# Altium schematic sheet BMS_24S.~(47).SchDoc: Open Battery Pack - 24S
size A3; Date: 26/03/2019; Author: Morgane Vallée - Samuel Lesueur; Revision: 1.0; SheetNumber: 3; SheetTotal: 5
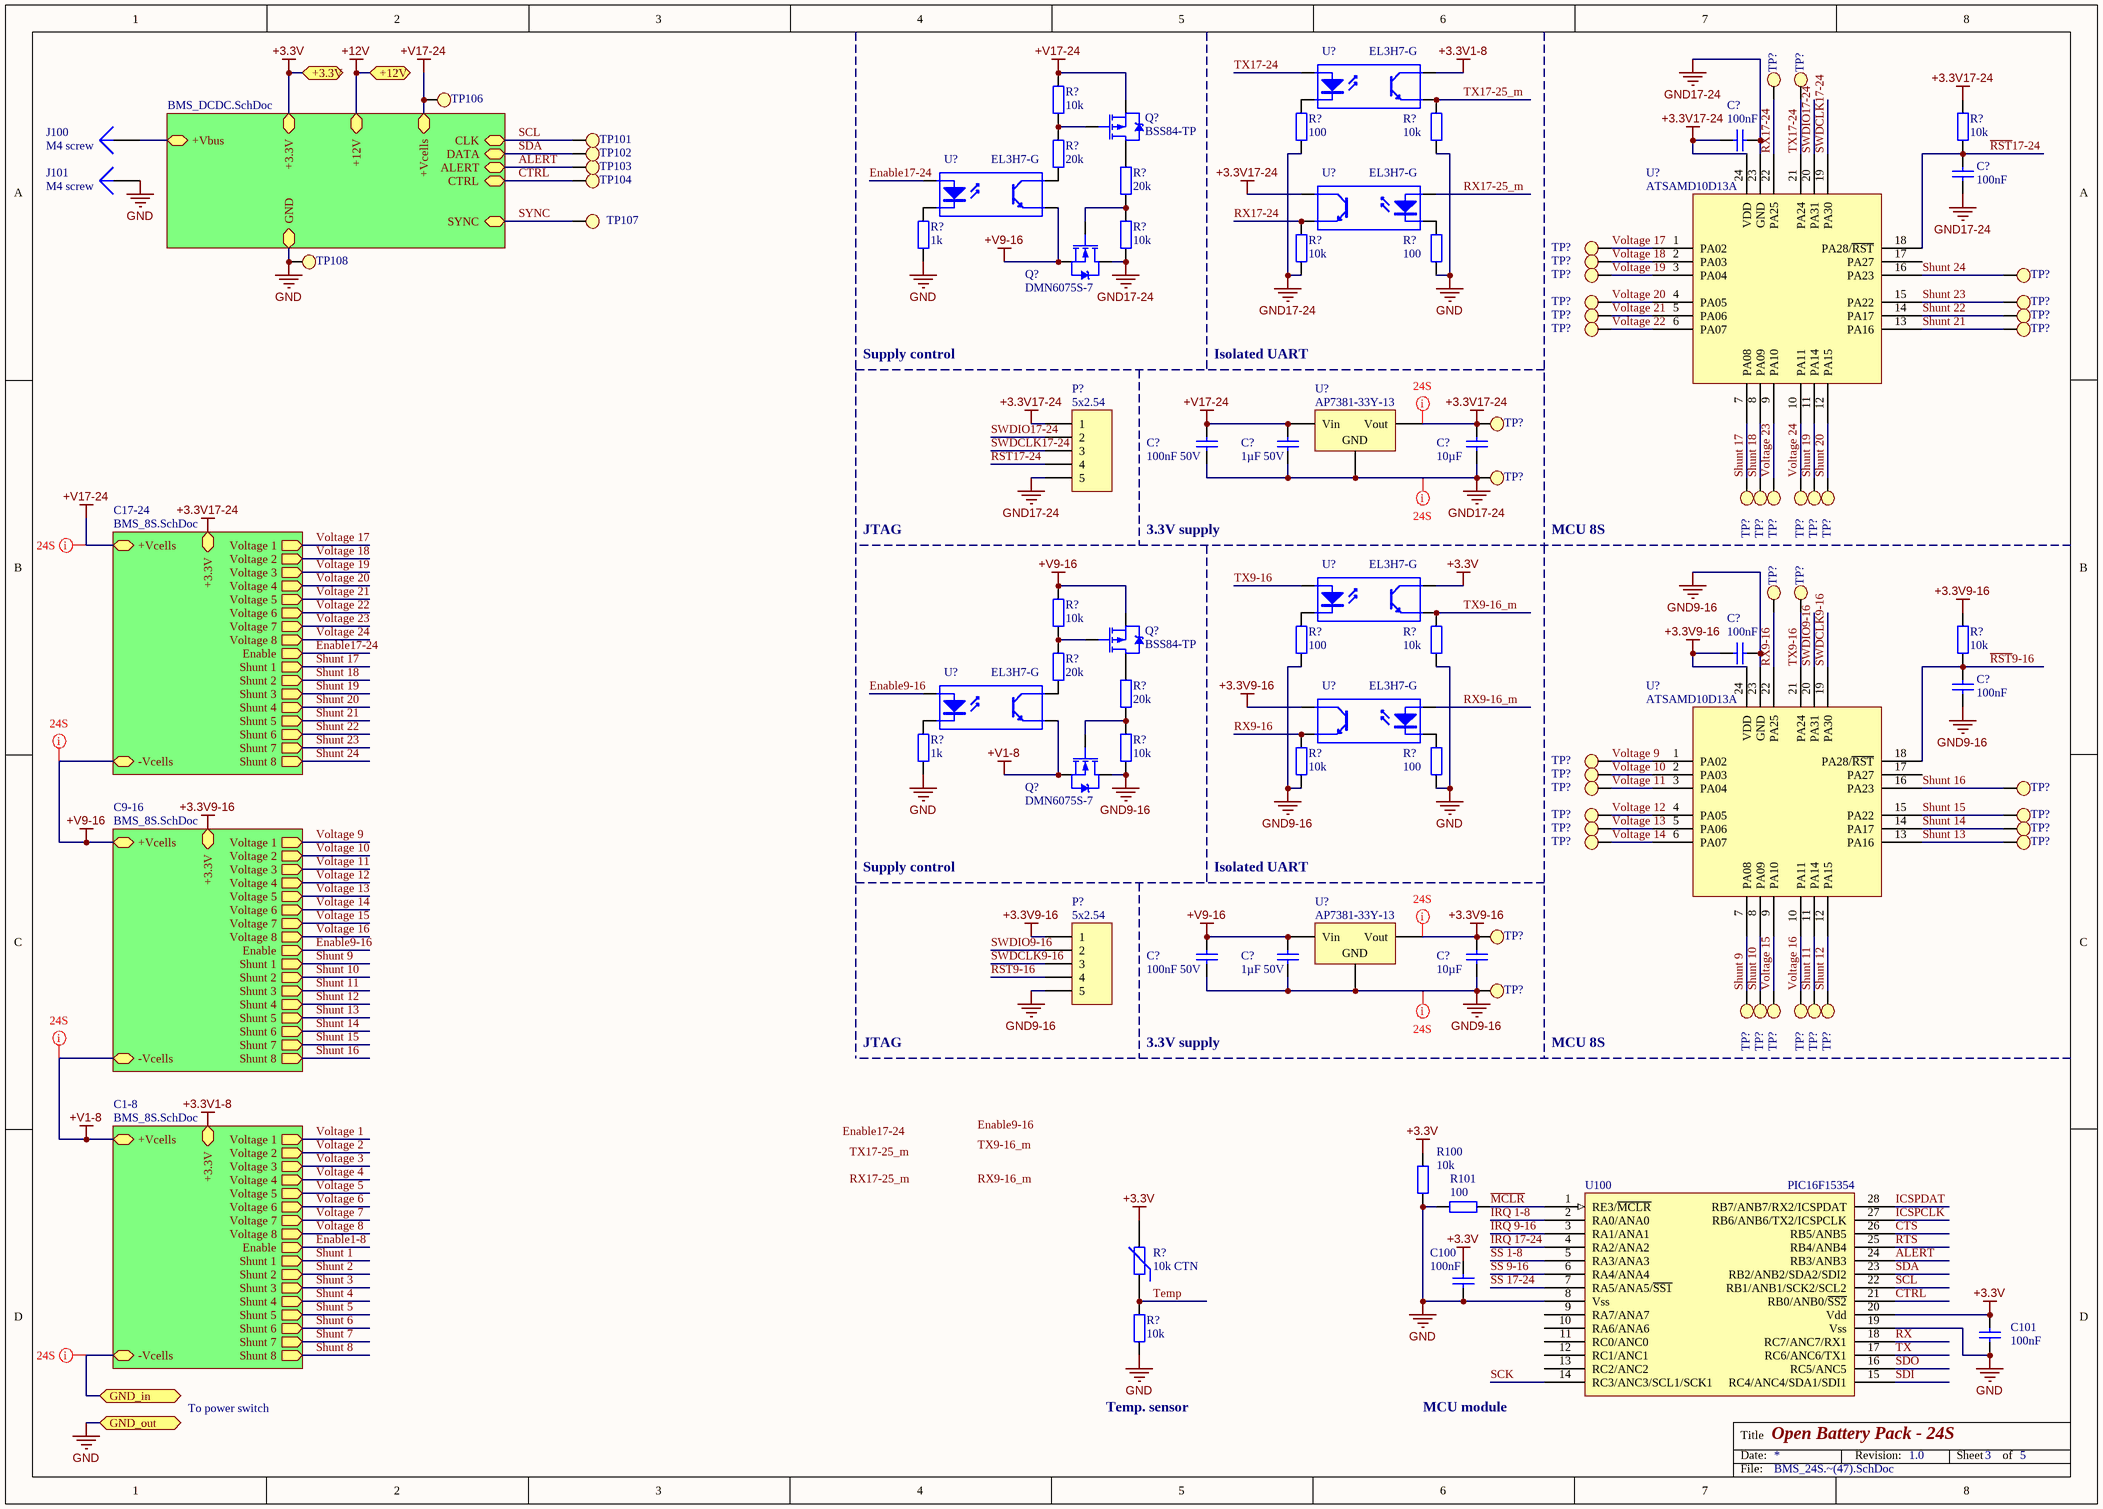
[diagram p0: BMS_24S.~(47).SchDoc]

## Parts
(Parts that share a designator on the sheet are numbered #1, #2 ... from top to bottom, then left to right.)
C100  100nF  [C0603]
C101  100nF  [C0603]
C?#1  100nF  [C0603]
C?#2  100nF  [C0603]
C?#3  100nF 50V  [C0603]
C?#4  1µF 50V  [C0805]
C?#5  10µF  [C0603]
C?#6  100nF  [C0603]
C?#7  100nF  [C0603]
C?#8  100nF 50V  [C0603]
C?#9  1µF 50V  [C0805]
C?#10  10µF  [C0603]
J100  M4 screw  [HOLE_4]
J101  M4 screw  [HOLE_4]
P?#1  5x2.54  [HDR1X5]
P?#2  5x2.54  [HDR1X5]
Q?#1  BSS84-TP  [DIODES SOT-23-3]
Q?#2  DMN6075S-7  [DIODES SOT-23-3]
Q?#3  BSS84-TP  [DIODES SOT-23-3]
Q?#4  DMN6075S-7  [DIODES SOT-23-3]
R100  10k  [R0603]
R101  100  [R0603]
R?#1  10k  [R0603]
R?#2  10k  [R0603]
R?#3  100  [R0603]
R?#4  10k  [R0603]
R?#5  20k  [R0603]
R?#6  20k  [R0603]
R?#7  100  [R0603]
R?#8  1k  [R0603]
R?#9  10k  [R0603]
R?#10  10k  [R0603]
R?#11  10k  [R0603]
R?#12  10k  [R0603]
R?#13  100  [R0603]
R?#14  10k  [R0603]
R?#15  20k  [R0603]
R?#16  20k  [R0603]
R?#17  100  [R0603]
R?#18  1k  [R0603]
R?#19  10k  [R0603]
R?#20  10k  [R0603]
R?#21  10k CTN  [NTC 0402/1005]
R?#22  10k  [R0603]
TP101  Test Point  [Test Point]  (value not drawn)
TP102  Test Point  [Test Point]  (value not drawn)
TP103  Test Point  [Test Point]  (value not drawn)
TP104  Test Point  [Test Point]  (value not drawn)
TP106  Test Point  [Test Point]  (value not drawn)
TP107  Test Point  [Test Point]  (value not drawn)
TP108  Test Point  [Test Point]  (value not drawn)
TP?#1  Test Point  [Test Point]  (value not drawn)
TP?#2  Test Point  [Test Point]  (value not drawn)
TP?#3  Test Point  [Test Point]  (value not drawn)
TP?#4  Test Point  [Test Point]  (value not drawn)
TP?#5  Test Point  [Test Point]  (value not drawn)
TP?#6  Test Point  [Test Point]  (value not drawn)
TP?#7  Test Point  [Test Point]  (value not drawn)
TP?#8  Test Point  [Test Point]  (value not drawn)
TP?#9  Test Point  [Test Point]  (value not drawn)
TP?#10  Test Point  [Test Point]  (value not drawn)
TP?#11  Test Point  [Test Point]  (value not drawn)
TP?#12  Test Point  [Test Point]  (value not drawn)
TP?#13  Test Point  [Test Point]  (value not drawn)
TP?#14  Test Point  [Test Point]  (value not drawn)
TP?#15  Test Point  [Test Point]  (value not drawn)
TP?#16  Test Point  [Test Point]  (value not drawn)
TP?#17  Test Point  [Test Point]  (value not drawn)
TP?#18  Test Point  [Test Point]  (value not drawn)
TP?#19  Test Point  [Test Point]  (value not drawn)
TP?#20  Test Point  [Test Point]  (value not drawn)
TP?#21  Test Point  [Test Point]  (value not drawn)
TP?#22  Test Point  [Test Point]  (value not drawn)
TP?#23  Test Point  [Test Point]  (value not drawn)
TP?#24  Test Point  [Test Point]  (value not drawn)
TP?#25  Test Point  [Test Point]  (value not drawn)
TP?#26  Test Point  [Test Point]  (value not drawn)
TP?#27  Test Point  [Test Point]  (value not drawn)
TP?#28  Test Point  [Test Point]  (value not drawn)
TP?#29  Test Point  [Test Point]  (value not drawn)
TP?#30  Test Point  [Test Point]  (value not drawn)
TP?#31  Test Point  [Test Point]  (value not drawn)
TP?#32  Test Point  [Test Point]  (value not drawn)
TP?#33  Test Point  [Test Point]  (value not drawn)
TP?#34  Test Point  [Test Point]  (value not drawn)
TP?#35  Test Point  [Test Point]  (value not drawn)
TP?#36  Test Point  [Test Point]  (value not drawn)
TP?#37  Test Point  [Test Point]  (value not drawn)
TP?#38  Test Point  [Test Point]  (value not drawn)
TP?#39  Test Point  [Test Point]  (value not drawn)
TP?#40  Test Point  [Test Point]  (value not drawn)
U100  PIC16F15354  [SSOP_28]
U?#1  EL3H7-G  [OPTO_EL3H7-G]
U?#2  EL3H7-G  [OPTO_EL3H7-G]
U?#3  EL3H7-G  [OPTO_EL3H7-G]
U?#4  ATSAMD10D13A  [SMSC QFN-24 4x4MM]
U?#5  AP7381-33Y-13  [ST SOIC-8N]
U?#6  EL3H7-G  [OPTO_EL3H7-G]
U?#7  EL3H7-G  [OPTO_EL3H7-G]
U?#8  EL3H7-G  [OPTO_EL3H7-G]
U?#9  ATSAMD10D13A  [SMSC QFN-24 4x4MM]
U?#10  AP7381-33Y-13  [ST SOIC-8N]

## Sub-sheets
C1-8 = BMS_8S.SchDoc: Voltage 6 (out), Shunt 2 (out), Shunt 7 (out), Shunt 6 (out), Voltage 3 (out), Voltage 5 (out), Shunt 8 (out), Voltage 8 (out), Voltage 7 (out), +3.3V, Voltage 2 (out), Shunt 4 (out), Shunt 3 (out), Shunt 5 (out), Voltage 4 (out), -Vcells, +Vcells, Shunt 1 (out), Voltage 1 (out), Enable (out)
C9-16 = BMS_8S.SchDoc: Voltage 6 (out), Shunt 2 (out), Shunt 7 (out), Shunt 6 (out), Voltage 3 (out), Voltage 5 (out), Shunt 8 (out), Voltage 8 (out), Voltage 7 (out), +3.3V, Voltage 2 (out), Shunt 4 (out), Shunt 3 (out), Shunt 5 (out), Voltage 4 (out), -Vcells, +Vcells, Shunt 1 (out), Voltage 1 (out), Enable (out)
C17-24 = BMS_8S.SchDoc: Voltage 6 (out), Shunt 2 (out), Shunt 7 (out), Shunt 6 (out), Voltage 3 (out), Voltage 5 (out), Shunt 8 (out), Voltage 8 (out), Voltage 7 (out), +3.3V, Voltage 2 (out), Shunt 4 (out), Shunt 3 (out), Shunt 5 (out), Voltage 4 (out), -Vcells, +Vcells, Shunt 1 (out), Voltage 1 (out), Enable (out)
? = BMS_DCDC.SchDoc: CTRL (bidir), SYNC (bidir), CLK (bidir), DATA (bidir), ALERT (bidir), GND, +3.3V, +Vbus, +Vcells, +12V

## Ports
+3.3V, +12V, GND_in, GND_out

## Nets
+3.3V: C100.2 C101.2 R100.2 R?#21.2 U100.20(Vdd) U?#6.4(C) ; port +3.3V, sheet /+3.3V
+3.3V1-8: U?#1.4(C) ; sheet C1-8/+3.3V
+3.3V9-16: C?#6.2 C?#10.1 P?#2.1 R?#14.2 TP?#33.1 U?#8.4(C) U?#9.24(VDD) U?#10.3(Vout) ; sheet C9-16/+3.3V
+3.3V17-24: C?#1.2 C?#5.1 P?#1.1 R?#4.2 TP?#13.1 U?#3.4(C) U?#4.24(VDD) U?#5.3(Vout) ; sheet C17-24/+3.3V
+12V: port +12V, sheet /+12V
+V1-8: Q?#4.2(S) U?#7.3(E) ; sheet C1-8/+Vcells, sheet C9-16/-Vcells
+V9-16: C?#8.1 C?#9.1 Q?#2.2(S) Q?#3.2(S) R?#11.2 U?#2.3(E) U?#10.1(Vin) ; sheet C9-16/+Vcells, sheet C17-24/-Vcells
+V17-24: C?#3.1 C?#4.1 Q?#1.2(S) R?#1.2 TP106.1 U?#5.1(Vin) ; sheet /+Vcells, sheet C17-24/+Vcells
GND: C100.1 C101.1 J101.1 R100.1 R101.2 R?#2.2 R?#7.2 R?#8.1 R?#12.2 R?#17.2 R?#18.1 R?#22.2 TP108.1 U100.8(Vss) U100.19(Vss) ; port GND_out, sheet /GND
GND9-16: C?#6.1 C?#7.1 C?#8.2 C?#9.2 C?#10.2 P?#2.5 Q?#4.3(D) R?#13.1 R?#19.1 R?#20.1 TP?#34.1 U?#9.23(GND) U?#10.2(GND)
GND17-24: C?#1.1 C?#2.1 C?#3.2 C?#4.2 C?#5.2 P?#1.5 Q?#2.3(D) R?#3.1 R?#9.1 R?#10.1 TP?#14.1 U?#4.23(GND) U?#5.2(GND)
ALERT: TP103.1 U100.24(RB3/ANB3) ; sheet /ALERT
CTRL: TP104.1 U100.21(RB0/ANB0/~{SS2}) ; sheet /CTRL
CTS: U100.26(RB5/ANB5)
Enable9-16: U?#7.1(A) ; sheet C9-16/Enable
Enable17-24: U?#2.1(A) ; sheet C17-24/Enable
GND_in: port GND_in, sheet C1-8/-Vcells
ICSPCLK: U100.27(RB6/ANB6/TX2/ICSPCLK)
ICSPDAT: U100.28(RB7/ANB7/RX2/ICSPDAT)
IRQ 1-8: U100.2(RA0/ANA0)
IRQ 9-16: U100.3(RA1/ANA1)
IRQ 17-24: U100.4(RA2/ANA2)
~{MCLR}: R101.1 U100.1(RE3/~{MCLR})
~{RST}9-16: C?#7.2 P?#2.4 R?#14.1 U?#9.18(PA28/~{RST})
~{RST}17-24: C?#2.2 P?#1.4 R?#4.1 U?#4.18(PA28/~{RST})
RTS: U100.25(RB4/ANB4)
RX: U100.18(RC7/ANC7/RX1)
RX9-16: R?#20.2 TP?#21.1 U?#8.3(E) U?#9.22(PA25)
RX9-16_m: U?#8.1(A)
RX17-24: R?#10.2 TP?#1.1 U?#3.3(E) U?#4.22(PA25)
RX17-25_m: U?#3.1(A)
~{SS} 1-8: U100.5(RA3/ANA3)
~{SS} 9-16: U100.6(RA4/ANA4)
~{SS} 17-24: U100.7(RA5/ANA5/~{SS1})
SCK: U100.14(RC3/ANC3/SCL1/SCK1)
SCL: TP101.1 U100.22(RB1/ANB1/SCK2/SCL2) ; sheet /CLK
SDA: TP102.1 U100.23(RB2/ANB2/SDA2/SDI2) ; sheet /DATA
SDI: U100.15(RC4/ANC4/SDA1/SDI1)
SDO: U100.16(RC5/ANC5)
Shunt 9: TP?#35.1 U?#9.7(PA08) ; sheet C9-16/Shunt 1
Shunt 10: TP?#36.1 U?#9.8(PA09) ; sheet C9-16/Shunt 2
Shunt 11: TP?#39.1 U?#9.11(PA14) ; sheet C9-16/Shunt 3
Shunt 12: TP?#40.1 U?#9.12(PA15) ; sheet C9-16/Shunt 4
Shunt 13: TP?#32.1 U?#9.13(PA16) ; sheet C9-16/Shunt 5
Shunt 14: TP?#30.1 U?#9.14(PA17) ; sheet C9-16/Shunt 6
Shunt 15: TP?#28.1 U?#9.15(PA22) ; sheet C9-16/Shunt 7
Shunt 16: TP?#26.1 U?#9.16(PA23) ; sheet C9-16/Shunt 8
Shunt 17: TP?#15.1 U?#4.7(PA08) ; sheet C17-24/Shunt 1
Shunt 18: TP?#16.1 U?#4.8(PA09) ; sheet C17-24/Shunt 2
Shunt 19: TP?#19.1 U?#4.11(PA14) ; sheet C17-24/Shunt 3
Shunt 20: TP?#20.1 U?#4.12(PA15) ; sheet C17-24/Shunt 4
Shunt 21: TP?#12.1 U?#4.13(PA16) ; sheet C17-24/Shunt 5
Shunt 22: TP?#10.1 U?#4.14(PA17) ; sheet C17-24/Shunt 6
Shunt 23: TP?#8.1 U?#4.15(PA22) ; sheet C17-24/Shunt 7
Shunt 24: TP?#6.1 U?#4.16(PA23) ; sheet C17-24/Shunt 8
SWDCLK9-16: P?#2.3 U?#9.19(PA30)
SWDCLK17-24: P?#1.3 U?#4.19(PA30)
SWDIO9-16: P?#2.2 U?#9.20(PA31)
SWDIO17-24: P?#1.2 U?#4.20(PA31)
SYNC: TP107.1 ; sheet /SYNC
Temp: R?#21.1 R?#22.1
TX: U100.17(RC6/ANC6/TX1)
TX9-16: TP?#22.1 U?#6.1(A) U?#9.21(PA24)
TX9-16_m: R?#12.1 U?#6.3(E)
TX17-24: TP?#2.1 U?#1.1(A) U?#4.21(PA24)
TX17-25_m: R?#2.1 U?#1.3(E)
Voltage 9: TP?#23.1 U?#9.1(PA02) ; sheet C9-16/Voltage 1
Voltage 10: TP?#24.1 U?#9.2(PA03) ; sheet C9-16/Voltage 2
Voltage 11: TP?#25.1 U?#9.3(PA04) ; sheet C9-16/Voltage 3
Voltage 12: TP?#27.1 U?#9.4(PA05) ; sheet C9-16/Voltage 4
Voltage 13: TP?#29.1 U?#9.5(PA06) ; sheet C9-16/Voltage 5
Voltage 14: TP?#31.1 U?#9.6(PA07) ; sheet C9-16/Voltage 6
Voltage 15: TP?#37.1 U?#9.9(PA10) ; sheet C9-16/Voltage 7
Voltage 16: TP?#38.1 U?#9.10(PA11) ; sheet C9-16/Voltage 8
Voltage 17: TP?#3.1 U?#4.1(PA02) ; sheet C17-24/Voltage 1
Voltage 18: TP?#4.1 U?#4.2(PA03) ; sheet C17-24/Voltage 2
Voltage 19: TP?#5.1 U?#4.3(PA04) ; sheet C17-24/Voltage 3
Voltage 20: TP?#7.1 U?#4.4(PA05) ; sheet C17-24/Voltage 4
Voltage 21: TP?#9.1 U?#4.5(PA06) ; sheet C17-24/Voltage 5
Voltage 22: TP?#11.1 U?#4.6(PA07) ; sheet C17-24/Voltage 6
Voltage 23: TP?#17.1 U?#4.9(PA10) ; sheet C17-24/Voltage 7
Voltage 24: TP?#18.1 U?#4.10(PA11) ; sheet C17-24/Voltage 8
NetJ100_1: J100.1 ; sheet /+Vbus
NetQ?#1_1: Q?#1.1(G) R?#1.1 R?#5.2
NetQ?#1_3: Q?#1.3(D) R?#6.2
NetQ?#2_1: Q?#2.1(G) R?#6.1 R?#9.2
NetQ?#3_1: Q?#3.1(G) R?#11.1 R?#15.2
NetQ?#3_3: Q?#3.3(D) R?#16.2
NetQ?#4_1: Q?#4.1(G) R?#16.1 R?#19.2
NetR?#3_2: R?#3.2 U?#1.2(K)
NetR?#5_1: R?#5.1 U?#2.4(C)
NetR?#7_1: R?#7.1 U?#3.2(K)
NetR?#8_2: R?#8.2 U?#2.2(K)
NetR?#13_2: R?#13.2 U?#6.2(K)
NetR?#15_1: R?#15.1 U?#7.4(C)
NetR?#17_1: R?#17.1 U?#8.2(K)
NetR?#18_2: R?#18.2 U?#7.2(K)

Not connected (* = marked no-connect by the designer): U100 9(RA7/ANA7) 10(RA6/ANA6) 11(RC0/ANC0) 12(RC1/ANC1) 13(RC2/ANC2); U?#4 17(PA27); U?#9 17(PA27)

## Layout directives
net class 24S: +3.3V9-16, +3.3V17-24, +V1-8, +V9-16, +V17-24, GND9-16, GND17-24, GND_in

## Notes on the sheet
- Supply control
- Isolated UART
- JTAG
- 3.3V supply
- MCU 8S
- To power switch
- Temp. sensor
- MCU module
- Labels drawn without touching a wire or pin: Enable9-16, Enable17-24, RX9-16_m, RX17-25_m, TX9-16_m, TX17-25_m

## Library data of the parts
C100 C101 C?#1-C?#10 = Cap: Capacitor
J100 J101 = Plug
P?#1 P?#2 = Header 5: Header, 5-Pin
Q?#1 Q?#3 = MOSFET_P
Q?#2 Q?#4 = MOSFET_N
R100 R101 R?#1-R?#20 R?#22 = Res2: Resistor
R?#21 = Res Varistor: Varistor (Voltage-Sensitive Resistor)
U?#1-U?#3 U?#6-U?#8 = Optoisolator1: 4-Pin Phototransistor Optocoupler
U?#5 U?#10 = Volt Reg: Voltage Regulator; pin to pad: 1>8 2>2+3+6+7 3>1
